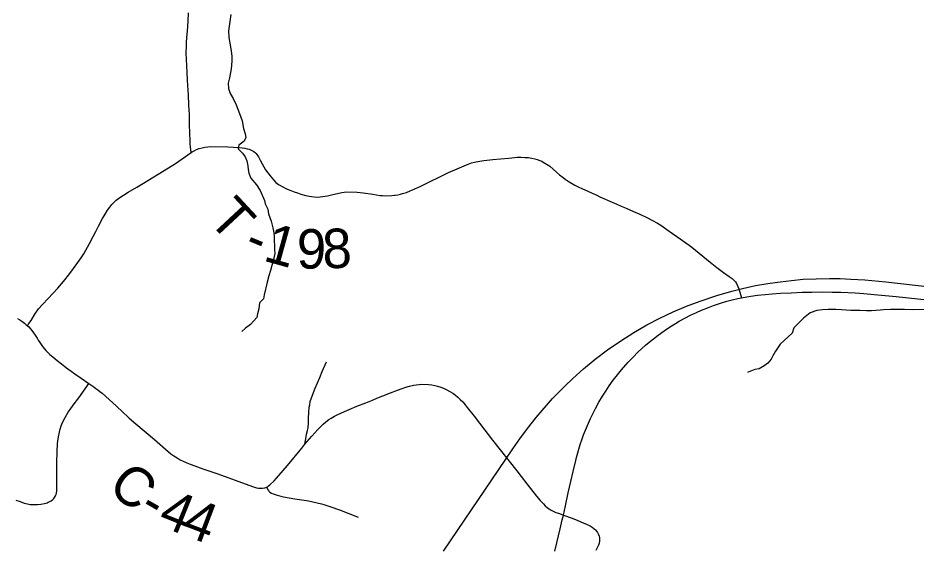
# Model space of a CAD drawing. Extents: x -7.1 to 34, y 0 to 22.
# Drawn here: x 2.831 to 4.122, y 16.88 to 17.646 of the extents above; entities that cross this region are included whole.
import ezdxf

# ---------------------------------------------------------------- set-up
doc = ezdxf.new("R2010")
doc.units = 0
for name, color, linetype in [('GM_X_County_Road', 7, 'Continuous'), ('GM_X_County_Road_Text', 7, 'Continuous'), ('GM_X_Minor_River', 7, 'Continuous'), ('GM_X_Rail_Line', 7, 'Continuous'), ('GM_X_State_Route', 7, 'Continuous'), ('GM_X_Township_Road', 7, 'Continuous'), ('GM_X_Township_Road_Text', 7, 'Continuous')]:
    doc.layers.add(name, color=color, linetype=linetype)

msp = doc.modelspace()

# ---------------------------------------------------------------- linework, layer by layer
at = {"layer": 'GM_X_County_Road'}
for points in [[(2.8298, 17.2132), (2.8334, 17.2111), (2.8363, 17.2092), (2.8401, 17.2064), (2.8421, 17.2047), (2.8443, 17.2027), (2.846, 17.2011), (2.848, 17.199), (2.8506, 17.196), (2.8531, 17.1926), (2.8554, 17.1891), (2.8582, 17.1848), (2.8598, 17.1822), (2.862, 17.1787), (2.8639, 17.1758), (2.8658, 17.173), (2.8686, 17.1698), (2.8707, 17.1673), (2.8736, 17.1642), (2.8765, 17.1615), (2.8805, 17.1581), (2.8871, 17.1528), (2.8933, 17.1478), (2.9004, 17.1424), (2.9069, 17.1376), (2.9123, 17.1337), (2.9215, 17.1274), (2.9325, 17.1196), (2.9397, 17.1147), (2.9426, 17.1126), (2.9454, 17.1105), (2.9484, 17.1081), (2.9515, 17.1056), (2.9562, 17.1015), (2.9621, 17.0963), (2.9719, 17.0874), (2.9816, 17.0782), (2.9882, 17.0721), (2.9904, 17.07), (3.0001, 17.0618), (3.0267, 17.039), (3.0466, 17.0218), (3.0504, 17.0187), (3.0548, 17.0156), (3.0596, 17.0125), (3.064, 17.01), (3.0682, 17.0078), (3.0734, 17.0055), (3.0784, 17.0035), (3.085, 17.0011), (3.0963, 16.9971), (3.1181, 16.9895), (3.1625, 16.9732), (3.1692, 16.9709), (3.1734, 16.9697), (3.1765, 16.9692), (3.1789, 16.969), (3.1824, 16.9691), (3.1854, 16.9696), (3.1869, 16.9701), (3.1879, 16.9705)], [(3.1879, 16.9705), (3.1893, 16.9712), (3.191, 16.9723), (3.1927, 16.9737), (3.1989, 16.9797), (3.2023, 16.9835), (3.2119, 16.9944), (3.2179, 17.0015), (3.2385, 17.0266), (3.2432, 17.0323), (3.2464, 17.0361), (3.2532, 17.044), (3.2617, 17.0537), (3.264, 17.0561), (3.2694, 17.0611), (3.2734, 17.0645), (3.2776, 17.0677), (3.281, 17.0699), (3.2857, 17.0726), (3.2893, 17.0745), (3.3001, 17.0796), (3.3068, 17.0825), (3.318, 17.087), (3.3306, 17.0921), (3.3402, 17.0959), (3.3468, 17.0986), (3.3554, 17.1021), (3.3664, 17.1064), (3.3765, 17.1103), (3.3831, 17.1127), (3.3881, 17.1143), (3.3937, 17.1159), (3.3991, 17.1172), (3.4032, 17.1178), (3.4074, 17.1183), (3.4113, 17.1186), (3.4209, 17.1183), (3.4256, 17.1177), (3.43, 17.1169), (3.4339, 17.1159), (3.4388, 17.1144), (3.4423, 17.113), (3.4462, 17.1111), (3.4527, 17.1076), (3.4557, 17.1058), (3.4595, 17.1031), (3.4632, 17.0999), (3.4664, 17.0969), (3.4701, 17.0931), (3.4738, 17.0889), (3.4767, 17.0854), (3.4867, 17.0727), (3.4942, 17.0628), (3.502, 17.0527), (3.5068, 17.0462), (3.5129, 17.0382), (3.548, 16.9941), (3.5543, 16.9858), (3.5625, 16.9751), (3.5762, 16.9577), (3.5815, 16.9513), (3.586, 16.9465), (3.5888, 16.9438), (3.5921, 16.9409), (3.5945, 16.9392), (3.5972, 16.9374), (3.6001, 16.9359), (3.6042, 16.9342), (3.6092, 16.9324), (3.6149, 16.9304)], [(3.1879, 16.9705), (3.1894, 16.9677), (3.1906, 16.9657), (3.1914, 16.9647), (3.1927, 16.9635), (3.1949, 16.9621), (3.1975, 16.961), (3.2019, 16.9594), (3.2085, 16.9576), (3.2126, 16.9567), (3.2286, 16.9537), (3.232, 16.9533), (3.2455, 16.9513), (3.2481, 16.9508), (3.2668, 16.9465), (3.2703, 16.9455), (3.2802, 16.9422), (3.2927, 16.9377), (3.3198, 16.9273)], [(3.6149, 16.9304), (3.6273, 16.9257), (3.6355, 16.9226), (3.6433, 16.9192), (3.6488, 16.9168), (3.6532, 16.9148), (3.6563, 16.913), (3.6588, 16.9112), (3.661, 16.9093), (3.6626, 16.9074), (3.664, 16.9054), (3.6654, 16.9026), (3.6661, 16.9001), (3.6667, 16.8979), (3.6667, 16.8965), (3.6667, 16.8929), (3.6662, 16.8901), (3.6653, 16.8871), (3.6636, 16.8833), (3.6617, 16.8792)]]:
    msp.add_lwpolyline(points, dxfattribs=at)
at = {"layer": 'GM_X_Minor_River'}
for points in [[(3.1367, 17.6509), (3.1335, 17.627), (3.134, 17.6175), (3.1352, 17.6095), (3.1373, 17.5985), (3.1382, 17.5901), (3.1383, 17.5833), (3.1373, 17.5726), (3.1348, 17.5596), (3.1326, 17.552), (3.1331, 17.544), (3.1355, 17.5371), (3.1398, 17.53), (3.1441, 17.5209), (3.1492, 17.508), (3.1527, 17.4978), (3.1548, 17.4868), (3.1572, 17.4788), (3.1584, 17.4739), (3.1558, 17.4685), (3.1483, 17.4627), (3.1472, 17.4573), (3.1534, 17.4513), (3.1573, 17.4457), (3.1596, 17.44), (3.1612, 17.4328), (3.1617, 17.4275), (3.1625, 17.4222), (3.1653, 17.4153), (3.1737, 17.4056), (3.1788, 17.3976), (3.185, 17.3829), (3.1859, 17.378), (3.1898, 17.3704), (3.1906, 17.3639), (3.1945, 17.3533), (3.1969, 17.3438), (3.1986, 17.3363), (3.199, 17.3306), (3.1993, 17.3127), (3.1997, 17.3069), (3.198, 17.2982), (3.1955, 17.2894), (3.1937, 17.2825), (3.1915, 17.2745), (3.189, 17.2657), (3.1847, 17.2473), (3.1836, 17.2416), (3.1777, 17.2358), (3.1767, 17.227), (3.1752, 17.2201), (3.1738, 17.2148), (3.169, 17.2094), (3.1649, 17.2044), (3.1577, 17.1993), (3.1525, 17.1946)], [(4.0506, 17.2244), (4.0411, 17.2246), (4.0332, 17.2249), (4.0283, 17.2248), (4.0214, 17.2251), (4.0146, 17.2258), (4.0067, 17.226), (4.001, 17.2263), (3.9957, 17.2262), (3.9873, 17.2257), (3.9794, 17.2248), (3.9696, 17.2213), (3.9599, 17.2135), (3.9464, 17.1996), (3.9439, 17.1923), (3.9267, 17.1764), (3.92, 17.1661), (3.916, 17.1595), (3.9134, 17.1545), (3.9086, 17.1491), (3.9037, 17.1449), (3.8962, 17.1409), (3.8901, 17.1397), (3.8807, 17.1361), (3.8798, 17.1357)], [(4.1411, 17.2262), (4.1168, 17.2258), (4.1055, 17.226), (4.093, 17.2262), (4.085, 17.2261), (4.0752, 17.2255), (4.0703, 17.2251), (4.0578, 17.2241), (4.0506, 17.2244)]]:
    msp.add_lwpolyline(points, dxfattribs=at)
at = {"layer": 'GM_X_Rail_Line'}
msp.add_lwpolyline([(3.4423, 16.8782), (3.5421, 17.0257), (3.552, 17.04), (3.5634, 17.055), (3.5755, 17.0706), (3.5992, 17.0982), (3.6169, 17.1161), (3.6283, 17.1271), (3.6437, 17.1407), (3.6603, 17.1546), (3.6782, 17.1681), (3.6972, 17.1811), (3.716, 17.1932), (3.735, 17.2039), (3.7536, 17.2137), (3.7728, 17.2228), (3.7919, 17.2309), (3.8114, 17.2384), (3.8353, 17.2464), (3.8568, 17.2524), (3.8725, 17.2565), (3.891, 17.2605), (3.9087, 17.2636), (3.9264, 17.2662), (3.9426, 17.2681), (3.9596, 17.2696), (3.9783, 17.2705), (3.9976, 17.2707), (4.0127, 17.2707), (4.028, 17.2698), (4.0482, 17.2687), (4.0785, 17.266), (4.2261, 17.2493)], dxfattribs=at)
at = {"layer": 'GM_X_State_Route'}
msp.add_lwpolyline([(3.6025, 16.8785), (3.6053, 16.8902), (3.6101, 16.9104), (3.6132, 16.9234), (3.6149, 16.9304), (3.6178, 16.9438), (3.6218, 16.9626), (3.6255, 16.9785), (3.6288, 16.9931), (3.6326, 17.009), (3.6337, 17.0134), (3.6355, 17.0199), (3.637, 17.0252), (3.639, 17.0318), (3.6413, 17.0386), (3.6439, 17.0458), (3.6479, 17.056), (3.6537, 17.0695), (3.6609, 17.0839), (3.666, 17.093), (3.671, 17.1013), (3.6757, 17.1089), (3.6805, 17.1165), (3.6863, 17.1245), (3.6924, 17.1323), (3.6986, 17.1396), (3.7079, 17.1503), (3.7157, 17.1583), (3.7218, 17.1646), (3.7328, 17.1747), (3.7381, 17.1791), (3.7445, 17.1842), (3.7513, 17.1893), (3.7595, 17.1954), (3.7672, 17.2008), (3.7762, 17.2062), (3.7814, 17.2093), (3.7895, 17.2139), (3.7978, 17.218), (3.8063, 17.222), (3.8135, 17.2252), (3.8237, 17.2293), (3.8308, 17.2319), (3.8409, 17.2353), (3.85, 17.2381), (3.8576, 17.2401), (3.8658, 17.242), (3.8711, 17.2431), (3.8785, 17.2446), (3.8845, 17.2455), (3.8938, 17.2467), (3.9049, 17.2478), (3.915, 17.2487), (3.9272, 17.2495), (3.9422, 17.2503), (3.9581, 17.2509), (3.9722, 17.2512), (3.9877, 17.2514), (4.0012, 17.2513), (4.0136, 17.251), (4.0342, 17.25), (4.047, 17.2492), (4.0619, 17.2479), (4.0934, 17.2447), (4.142, 17.2395)], dxfattribs=at)
at = {"layer": 'GM_X_Township_Road'}
for points in [[(3.0794, 17.4522), (3.0789, 17.4566), (3.0787, 17.4598), (3.0784, 17.4648), (3.0782, 17.469), (3.0774, 17.4917), (3.077, 17.507), (3.0764, 17.5204), (3.0758, 17.5352), (3.075, 17.5486), (3.0745, 17.5564), (3.0738, 17.5671), (3.0732, 17.5767), (3.0727, 17.5866), (3.0725, 17.5951), (3.0727, 17.6055), (3.0729, 17.6102), (3.0735, 17.6175), (3.0741, 17.6267), (3.0751, 17.6409), (3.0759, 17.6531)], [(2.8443, 17.2027), (2.8463, 17.2058), (2.8494, 17.2105), (2.8549, 17.2194), (2.8601, 17.227), (2.8656, 17.2336), (2.8738, 17.242), (2.8809, 17.2493), (2.8879, 17.2571), (2.8958, 17.2664), (2.9049, 17.2779), (2.9104, 17.2851), (2.9165, 17.2938), (2.9215, 17.3004), (2.9255, 17.3063), (2.9335, 17.3213), (2.9387, 17.3314), (2.9425, 17.3386), (2.9464, 17.346), (2.9523, 17.3573), (2.9561, 17.3636), (2.9595, 17.369), (2.9625, 17.3732), (2.9657, 17.3771), (2.9687, 17.3804), (2.972, 17.3835), (2.9749, 17.3858), (2.9784, 17.3882), (2.9822, 17.3905), (2.9892, 17.3949), (3.0014, 17.4021), (3.011, 17.4078), (3.0472, 17.4298), (3.057, 17.4363), (3.0669, 17.4429), (3.0794, 17.4522), (3.0811, 17.4532), (3.0839, 17.4547), (3.0873, 17.4563), (3.0913, 17.4577), (3.0952, 17.4588), (3.0992, 17.4597), (3.1035, 17.4603), (3.1078, 17.4606), (3.1322, 17.4604), (3.1405, 17.4597), (3.1475, 17.4591), (3.1527, 17.4587), (3.1568, 17.4582), (3.16, 17.4575), (3.1632, 17.4567), (3.1657, 17.4557), (3.168, 17.4546), (3.1699, 17.4534), (3.1719, 17.4518), (3.1733, 17.4505), (3.1765, 17.4458), (3.1789, 17.4412), (3.1819, 17.4357), (3.1865, 17.4274), (3.1931, 17.4183), (3.1979, 17.4126), (3.2014, 17.4089), (3.2053, 17.406), (3.2114, 17.4025), (3.2169, 17.3997), (3.223, 17.3973), (3.2278, 17.3956), (3.2324, 17.3939), (3.2371, 17.3923), (3.2447, 17.3902), (3.2491, 17.3893), (3.2532, 17.3886), (3.2567, 17.3882), (3.2606, 17.388), (3.2651, 17.3882), (3.2691, 17.3887), (3.2755, 17.3899), (3.2833, 17.3916), (3.2902, 17.3932), (3.2961, 17.3945), (3.3029, 17.3953), (3.3182, 17.3951), (3.3269, 17.3942), (3.3407, 17.3921), (3.3512, 17.3904), (3.3547, 17.39), (3.3584, 17.3898), (3.3682, 17.3902), (3.3721, 17.3907), (3.3731, 17.3908), (3.3766, 17.3914), (3.3804, 17.3923), (3.3837, 17.3932), (3.3891, 17.3947), (3.3945, 17.3968), (3.3971, 17.3978), (3.4097, 17.4038), (3.4498, 17.4231), (3.462, 17.4287), (3.472, 17.433), (3.4777, 17.4352), (3.4826, 17.437), (3.487, 17.4381), (3.4916, 17.4391), (3.5005, 17.4404), (3.5134, 17.4418), (3.5243, 17.4429), (3.5362, 17.444), (3.5406, 17.4446), (3.5486, 17.4452), (3.5534, 17.4453), (3.5592, 17.4451), (3.5647, 17.4447), (3.5694, 17.444), (3.5736, 17.4432), (3.5773, 17.4422), (3.581, 17.4408), (3.584, 17.4394), (3.5858, 17.4384), (3.5937, 17.4334), (3.5953, 17.4323), (3.6051, 17.4238), (3.6092, 17.4201), (3.6143, 17.416), (3.6176, 17.4135), (3.6229, 17.4101), (3.629, 17.4064), (3.6312, 17.405), (3.636, 17.4027), (3.6423, 17.3997), (3.6488, 17.3968), (3.6561, 17.3935), (3.6627, 17.3905), (3.6671, 17.3885), (3.6705, 17.3869), (3.6815, 17.382), (3.6915, 17.3777), (3.6981, 17.3749), (3.7053, 17.3719), (3.7157, 17.3674), (3.7246, 17.3634), (3.7347, 17.3585), (3.7431, 17.3542), (3.7503, 17.3503), (3.7549, 17.3476), (3.7585, 17.3452), (3.7635, 17.3415), (3.7717, 17.3355), (3.7778, 17.3314), (3.7957, 17.3186), (3.7994, 17.3158), (3.8258, 17.2944), (3.8357, 17.2866), (3.8451, 17.2796), (3.8531, 17.2739), (3.8574, 17.2708), (3.8596, 17.2689), (3.8621, 17.266), (3.8637, 17.2635), (3.8657, 17.2593), (3.867, 17.2558), (3.8686, 17.251), (3.8711, 17.2431)], [(3.2432, 17.0323), (3.2448, 17.043), (3.2455, 17.047), (3.2468, 17.0521), (3.2472, 17.0538), (3.2476, 17.0559), (3.2479, 17.0577), (3.2481, 17.0611), (3.2483, 17.0649), (3.2485, 17.0715), (3.2487, 17.0761), (3.249, 17.0808), (3.2491, 17.083), (3.2494, 17.0858), (3.25, 17.0892), (3.2509, 17.0936), (3.2554, 17.1067), (3.2578, 17.1128), (3.2645, 17.1283), (3.2681, 17.1369), (3.2743, 17.1509)], [(2.8277, 16.9519), (2.8339, 16.9498), (2.8397, 16.9477), (2.8444, 16.9464), (2.8482, 16.9458), (2.8514, 16.9455), (2.8547, 16.9454), (2.8585, 16.9455), (2.8634, 16.9461), (2.8685, 16.9471), (2.8724, 16.9481), (2.8742, 16.9488), (2.8765, 16.9499), (2.8785, 16.9511), (2.8805, 16.9527), (2.8821, 16.9544), (2.8831, 16.9556), (2.8845, 16.9581), (2.8853, 16.9601), (2.886, 16.9625), (2.8863, 16.9648), (2.8865, 16.9671), (2.8864, 16.9777), (2.8863, 16.9906), (2.8864, 16.9966), (2.8865, 17.0074), (2.8869, 17.02), (2.887, 17.0248), (2.8873, 17.0298), (2.8876, 17.0336), (2.8879, 17.0368), (2.8888, 17.0428), (2.8902, 17.0498), (2.8913, 17.054), (2.8927, 17.0586), (2.8945, 17.0634), (2.8982, 17.0706), (2.9029, 17.0784), (2.9058, 17.0824), (2.91, 17.0884), (2.918, 17.0991), (2.9272, 17.1118), (2.9296, 17.1152), (2.9325, 17.1196)]]:
    msp.add_lwpolyline(points, dxfattribs=at)

# ---------------------------------------------------------------- texts
at = {"layer": 'GM_X_County_Road_Text'}
for s, rotation, p in [('C', 320.8111, (2.9576, 16.9673)), ('4', 338.0023, (3.0299, 16.9168)), ('-', 330.1136, (3.002, 16.9322)), ('4', 339.2912, (3.0637, 16.9032))]:
    msp.add_text(s, height=0.0568, rotation=rotation, dxfattribs=at).set_placement(p)
at = {"layer": 'GM_X_Township_Road_Text'}
for s, rotation, p in [('T', 312.9085, (3.1023, 17.3545)), ('1', 344.5113, (3.1816, 17.2969)), ('8', 2.1213, (3.2692, 17.285)), ('-', 337.4934, (3.1529, 17.3083)), ('9', 359.3184, (3.2311, 17.2853))]:
    msp.add_text(s, height=0.0568, rotation=rotation, dxfattribs=at).set_placement(p)

doc.saveas('drawing.dxf')
